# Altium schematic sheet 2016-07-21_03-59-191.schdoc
size 469 x 147 mm; SheetNumber: 1; SheetTotal: 1
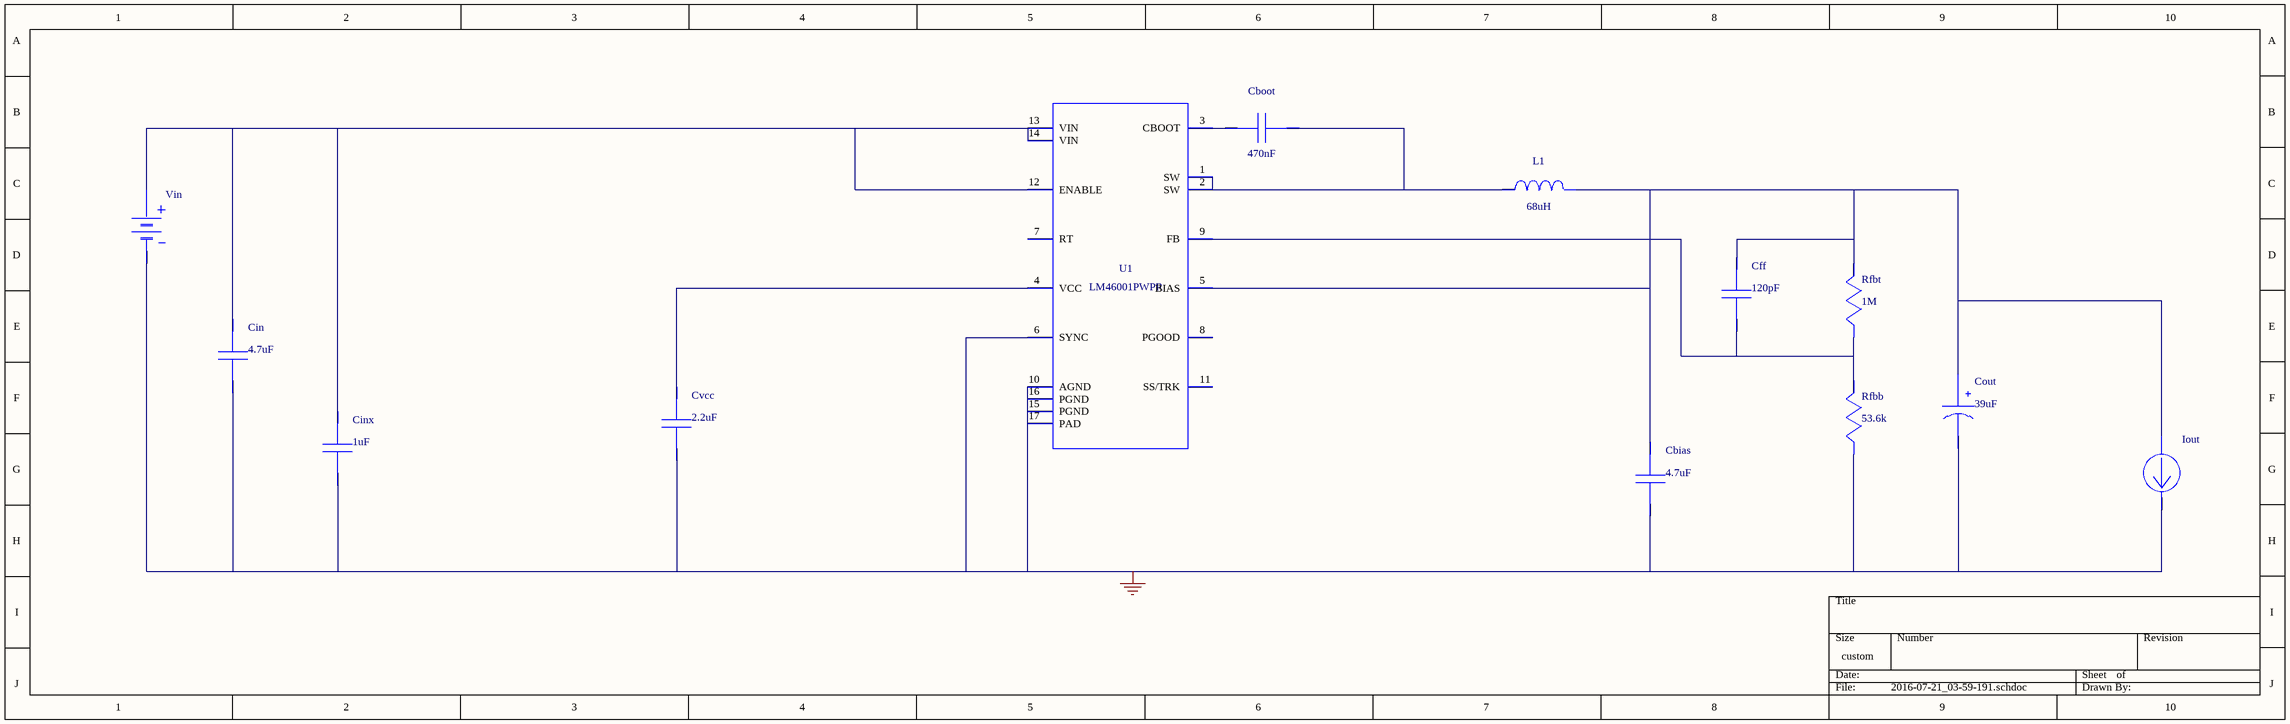
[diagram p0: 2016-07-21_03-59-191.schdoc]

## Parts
Cbias  value 4.7uF  (hidden comment: GRM31CR71H475KA12L)
Cboot  value 470nF  (hidden comment: GRM155C80J474KE19D)
Cff  value 120pF  (hidden comment: C0805C121J5GACTU)
Cin  value 4.7uF  (hidden comment: C3225X7S2A475M200AB)
Cinx  value 1uF  (hidden comment: C3216X5R2A105K)
Cout  value 39uF  (hidden comment: 35SVPF39M)
Cvcc  value 2.2uF  (hidden comment: GRM155R60J225ME15D)
Iout  WB_CURRENT_LOAD  (value not drawn)
L1  value 68uH  (hidden comment: 'LPS8045B-683MRB')
Rfbb  value 53.6k  (hidden comment: CRCW040253K6FKED)
Rfbt  value 1M  (hidden comment: CRCW04021M00FKED)
U1  LM43603PWPR  (value not drawn)
Vin  WB_BATTERY  (value not drawn)

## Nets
0: Cbias.2 Cin.2 Cinx.2 Cout.2(-) Cvcc.2 Iout.2(-) Rfbb.2 U1.6(SYNC) U1.10(AGND) U1.15(PGND) U1.16(PGND) U1.17(PAD) Vin.2(-)
NetCbias_1: Cbias.1 Cff.1 Cout.1(+) Iout.1(+) L1.2 Rfbt.1 U1.5(BIAS)
NetCboot_1: Cboot.1 L1.1 U1.1(SW) U1.2(SW)
NetCboot_2: Cboot.2 U1.3(CBOOT)
NetCff_2: Cff.2 Rfbb.1 Rfbt.2 U1.9(FB)
NetCin_1: Cin.1 Cinx.1 U1.12(ENABLE) U1.13(VIN) U1.14(VIN) Vin.1(+)
NetCvcc_1: Cvcc.1 U1.4(VCC)

Not connected (* = marked no-connect by the designer): U1 7(RT) 8(PGOOD) 11(SS/TRK)

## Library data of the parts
Cbias = GRM31CR71H475KA12L: GRM31CR71H475KA1; Manufacturer Name: MuRata
Cboot = GRM155C80J474KE19D: GRM155C80J474KE1; Manufacturer Name: MuRata
Cff = C0805C121J5GACTU: Manufacturer Name: Kemet
Cin = C3225X7S2A475M200AB: C3225X7S2A475M20; Manufacturer Name: TDK
Cinx = C3216X5R2A105K: Manufacturer Name: TDK
Cout = 35SVPF39M: Manufacturer Name: Panasonic
Cvcc = GRM155R60J225ME15D: GRM155R60J225ME1; Manufacturer Name: MuRata
L1 = 'LPS8045B-683MRB': LPS8045B-683MRB; Manufacturer Name: Coilcraft
Rfbb = CRCW040253K6FKED: Manufacturer Name: Vishay-Dale
Rfbt = CRCW04021M00FKED: Manufacturer Name: Vishay-Dale
U1 = LM43603PWPR: LM46001PWPR; Manufacturer Name: Texas Instruments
